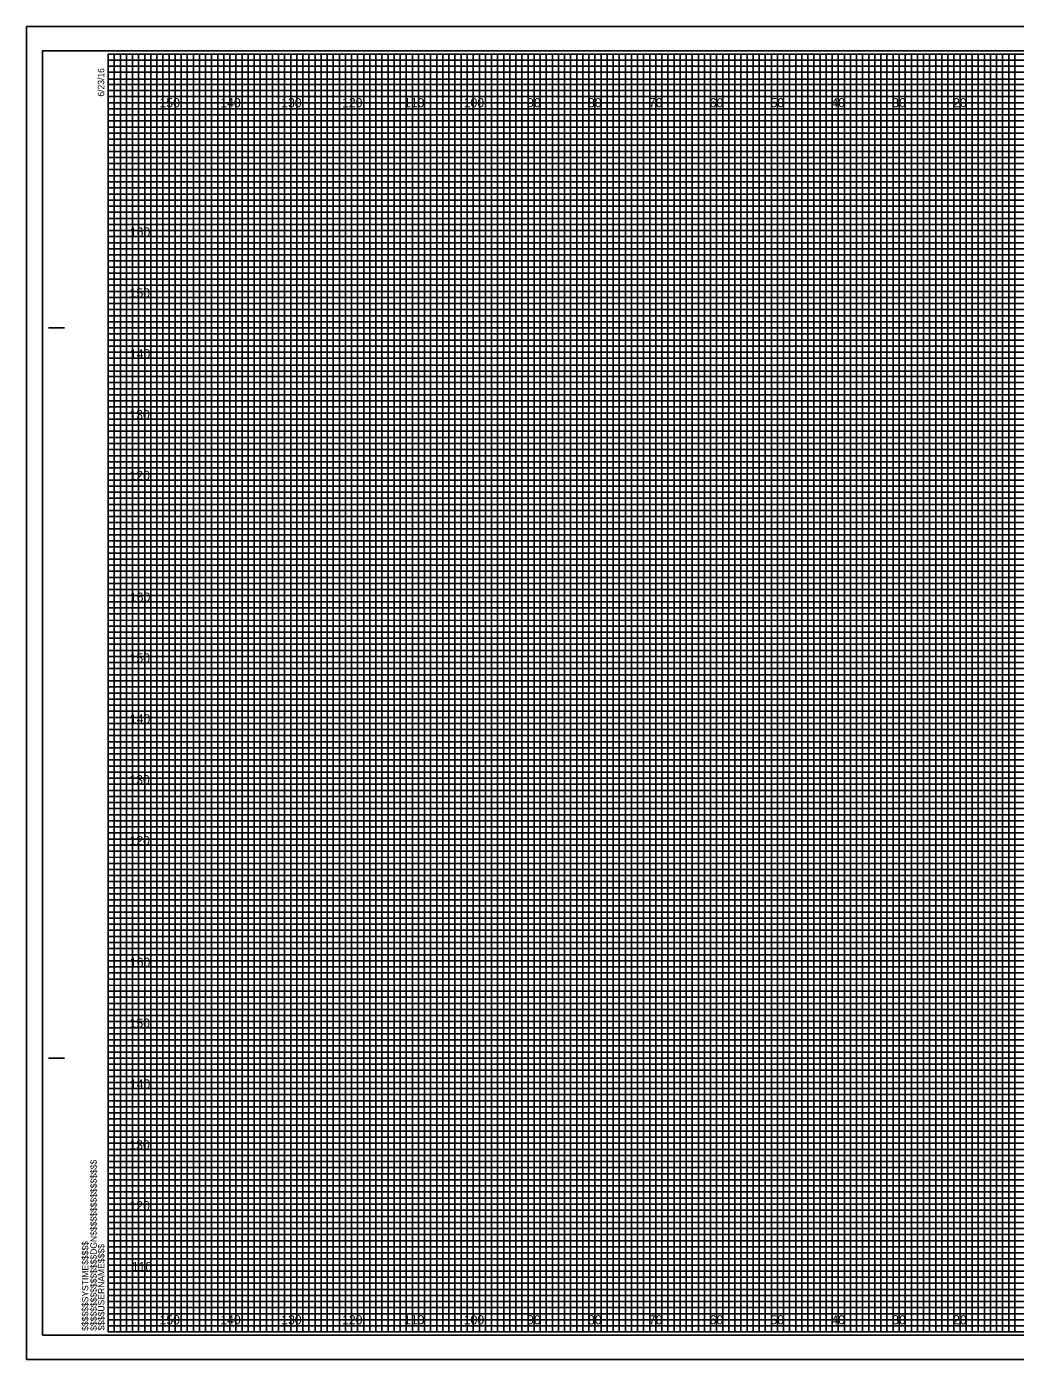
# Model space of a CAD drawing. Extents: x -13 to 323, y -5 to 1974.
# Drawn here: x -13.4 to 149.1, y 1095.5 to 1314.5 of the extents above; entities that cross this region are included whole.
import ezdxf

# ---------------------------------------------------------------- set-up
doc = ezdxf.new("R2010")
doc.units = 0
for name, color, linetype in [('Exist Cross Section Cell', 7, 'Continuous'), ('Exist XS Center Line Elevation Label', 7, 'Continuous'), ('Exist XS Ground Line', 7, 'Continuous'), ('Prop CMT Pvmt Course 1', 7, 'Continuous'), ('Prop CMT Pvmt Course 3', 7, 'Continuous'), ('Prop CMT Pvmt Surface', 7, 'Continuous'), ('Prop CMT Pvmt Surface Shoulder', 7, 'Continuous'), ('Prop CMT Shld Paved Course 1', 7, 'Continuous'), ('Prop CMT Shld Paved Course 2', 7, 'Continuous'), ('Prop CMT Shld Paved Course 3', 7, 'Continuous'), ('Prop CMT Subgrade Earthwork', 7, 'Continuous')]:
    doc.layers.add(name, color=color, linetype=linetype)

msp = doc.modelspace()

# ---------------------------------------------------------------- linework, layer by layer
at = {"layer": 'Exist XS Center Line Elevation Label'}
for points in [[(0, 1310), (5, 1310), (5, 1100), (15, 1100), (15, 1310), (25, 1310), (25, 1100), (35, 1100), (35, 1310), (45, 1310), (45, 1100), (55, 1100), (55, 1310), (65, 1310), (65, 1100), (75, 1100), (75, 1310), (85, 1310), (85, 1100), (95, 1100), (95, 1310), (105, 1310), (105, 1100), (115, 1100), (115, 1310), (125, 1310), (125, 1100), (135, 1100), (135, 1310), (145, 1310), (145, 1100), (155, 1100)], [(0, 1305), (275, 1305)], [(0, 1285), (320, 1285), (320, 1295), (0, 1295)], [(0, 1265), (320, 1265), (320, 1275), (0, 1275)], [(0, 1245), (320, 1245), (320, 1255), (0, 1255)], [(0, 1225), (320, 1225), (320, 1235), (0, 1235)], [(0, 1205), (320, 1205), (320, 1215), (0, 1215)], [(0, 1185), (320, 1185), (320, 1195), (0, 1195)], [(0, 1165), (320, 1165), (320, 1175), (0, 1175)], [(0, 1145), (320, 1145), (320, 1155), (0, 1155)], [(0, 1125), (320, 1125), (320, 1135), (0, 1135)], [(0, 1105), (320, 1105), (320, 1115), (0, 1115)]]:
    msp.add_lwpolyline(points, dxfattribs=at)
at = {"layer": 'Exist XS Ground Line'}
for p, q in [((10, 1310), (0, 1310)), ((10, 1100), (10, 1310)), ((30, 1310), (20, 1310)), ((20, 1310), (20, 1100)), ((30, 1100), (30, 1310)), ((50, 1310), (40, 1310)), ((40, 1310), (40, 1100)), ((50, 1100), (50, 1310)), ((70, 1310), (60, 1310)), ((60, 1310), (60, 1100)), ((70, 1100), (70, 1310)), ((90, 1310), (80, 1310)), ((80, 1310), (80, 1100)), ((90, 1100), (90, 1310)), ((110, 1310), (100, 1310)), ((100, 1310), (100, 1100)), ((110, 1100), (110, 1310)), ((130, 1310), (120, 1310)), ((120, 1310), (120, 1100)), ((130, 1100), (130, 1310)), ((150, 1310), (140, 1310)), ((140, 1310), (140, 1100)), ((20, 1100), (10, 1100)), ((40, 1100), (30, 1100)), ((60, 1100), (50, 1100)), ((80, 1100), (70, 1100)), ((100, 1100), (90, 1100)), ((120, 1100), (110, 1100)), ((140, 1100), (130, 1100))]:
    msp.add_line(p, q, dxfattribs=at)
for points in [[(0, 1300), (320, 1300), (320, 1290), (0, 1290)], [(0, 1280), (320, 1280), (320, 1270), (0, 1270)], [(0, 1260), (320, 1260), (320, 1250), (0, 1250)], [(0, 1240), (320, 1240), (320, 1230), (0, 1230)], [(0, 1220), (320, 1220), (320, 1210), (0, 1210)], [(0, 1200), (320, 1200), (320, 1190), (0, 1190)], [(0, 1180), (320, 1180), (320, 1170), (0, 1170)], [(0, 1160), (320, 1160), (320, 1150), (0, 1150)], [(0, 1140), (320, 1140), (320, 1130), (0, 1130)], [(0, 1120), (320, 1120), (320, 1110), (0, 1110)]]:
    msp.add_lwpolyline(points, dxfattribs=at)
at = {"layer": 'Prop CMT Pvmt Course 3'}
msp.add_lwpolyline([(-13.4, 1095.5), (323.3, 1095.5), (323.3, 1314.5), (-13.4, 1314.5)], close=True, dxfattribs=at)
at = {"layer": 'Prop CMT Pvmt Surface'}
for p, q in [((10, 1100), (10, 1310)), ((20, 1100), (20, 1310)), ((30, 1100), (30, 1310)), ((40, 1100), (40, 1310)), ((50, 1100), (50, 1310)), ((60, 1100), (60, 1310)), ((70, 1100), (70, 1310)), ((80, 1100), (80, 1310)), ((90, 1100), (90, 1310)), ((100, 1100), (100, 1310)), ((110, 1100), (110, 1310)), ((120, 1100), (120, 1310)), ((130, 1100), (130, 1310)), ((140, 1100), (140, 1310)), ((0, 1300), (320, 1300)), ((0, 1290), (320, 1290)), ((0, 1280), (320, 1280)), ((0, 1270), (320, 1270)), ((0, 1260), (320, 1260)), ((0, 1250), (320, 1250)), ((0, 1240), (320, 1240)), ((0, 1230), (320, 1230)), ((0, 1220), (320, 1220)), ((0, 1210), (320, 1210)), ((0, 1200), (320, 1200)), ((0, 1190), (320, 1190)), ((0, 1180), (320, 1180)), ((0, 1170), (320, 1170)), ((0, 1160), (320, 1160)), ((0, 1150), (320, 1150)), ((0, 1140), (320, 1140)), ((0, 1130), (320, 1130)), ((0, 1120), (320, 1120)), ((0, 1110), (320, 1110))]:
    msp.add_line(p, q, dxfattribs=at)
at = {"layer": 'Prop CMT Pvmt Surface Shoulder'}
for p, q in [((323.3, 1314.5), (-13.4, 1314.5)), ((-13.4, 1314.5), (-13.4, 1095.5)), ((-13.4, 1095.5), (323.3, 1095.5))]:
    msp.add_line(p, q, dxfattribs=at)
at = {"layer": 'Prop CMT Shld Paved Course 1'}
for p, q in [((0, 1309), (260, 1309)), ((260, 1307.98), (0, 1307.98)), ((0, 1307.98), (0, 1307)), ((0, 1307), (260, 1307)), ((260, 1305.89), (0, 1305.89)), ((0, 1305.89), (0, 1304)), ((0, 1304), (320, 1304))]:
    msp.add_line(p, q, dxfattribs=at)
for points in [[(0, 1303), (270, 1303), (320, 1303), (320, 1302), (0, 1302)], [(0, 1301), (320, 1301), (320, 1299), (0, 1299)], [(0, 1298), (320, 1298), (320, 1297), (0, 1296.98)], [(0, 1296), (320, 1296), (320, 1294), (0, 1294)], [(0, 1293), (320, 1293), (320, 1292), (0, 1292)], [(0, 1291), (320, 1291), (320, 1289), (0, 1289)], [(0, 1288), (320, 1288), (320, 1287), (0, 1287)], [(0, 1286), (320, 1286), (320, 1284), (0, 1284)], [(0, 1283), (320, 1283), (320, 1282), (0, 1282)], [(0, 1281), (320, 1281), (320, 1279), (0, 1279)], [(0, 1278), (320, 1278), (320, 1277), (0, 1277)], [(0, 1276), (320, 1276), (320, 1273.95), (320, 1273), (320, 1272), (0, 1272)], [(0, 1274), (320, 1274), (320, 1273), (0, 1273)], [(0, 1271), (320, 1271), (320, 1269), (0, 1269.03)], [(0, 1269.03), (320, 1269), (320, 1268), (0, 1268)], [(0, 1267), (320, 1267), (320, 1266), (0, 1266)], [(0, 1264), (320, 1264), (320, 1263), (0, 1263)], [(0, 1262), (320, 1262), (320, 1261), (0, 1261)], [(-0.07, 1258.89), (320, 1258.89), (320, 1257.88), (-0.07, 1257.88)], [(0, 1257), (320, 1257), (320, 1256), (0, 1256)], [(0, 1254), (320, 1254), (320, 1253), (0, 1253)], [(0, 1252), (320, 1252), (320, 1251), (0, 1251)], [(0, 1249), (320, 1249), (320, 1248), (0, 1248)], [(0, 1247), (320, 1247), (320, 1246), (0, 1246)], [(0, 1244), (320, 1244), (320, 1243), (0, 1243)], [(0, 1242), (320, 1242), (320, 1241), (0, 1241)], [(0, 1239), (320, 1239), (319.99, 1237.98), (0, 1238)], [(0, 1237), (320, 1237), (320, 1236), (0, 1236)], [(0, 1234), (320, 1234), (320, 1233), (0, 1233)], [(0, 1232), (320, 1232), (320, 1231), (0, 1231)], [(0, 1229), (320, 1229), (320, 1228), (0, 1228)], [(0, 1227), (320, 1227), (320, 1226), (0, 1226)], [(0, 1224), (320, 1224), (320, 1223), (0, 1223)], [(0, 1222), (320, 1222), (320, 1221), (0, 1221)], [(0, 1219), (320, 1219), (320, 1218), (0, 1218)], [(0, 1216.99), (320.07, 1216.91), (320, 1216), (0, 1216)], [(0, 1214), (320, 1214), (320, 1213), (0, 1213)], [(0, 1212), (320, 1212), (320, 1211), (0, 1211)], [(0, 1209), (320, 1209), (320, 1208), (0, 1208)], [(0, 1207), (320, 1207), (320, 1206), (0, 1206)], [(0, 1204), (320, 1204), (320, 1203), (0, 1203)], [(0, 1202), (320, 1202), (320, 1201), (0, 1201)], [(0, 1199), (320, 1199), (320, 1198), (0, 1198)], [(0, 1197), (320, 1197), (320, 1196), (0, 1196)], [(0, 1194), (320, 1194), (320, 1193), (0, 1193)], [(0, 1192), (320, 1192), (320, 1191), (0, 1191)], [(0, 1189), (320, 1189), (320, 1188), (0, 1188)], [(0, 1187), (320, 1187), (320, 1186), (0, 1186)], [(0, 1184), (320, 1184), (320, 1183), (0, 1183)], [(0, 1182), (320, 1182), (320, 1181), (0, 1181)], [(0, 1179), (320, 1179), (319.99, 1177.98), (0, 1178)], [(0, 1177), (320, 1177), (320, 1176), (0, 1176)], [(0, 1174), (320, 1174), (320, 1173), (0, 1173)], [(0, 1172), (320, 1172), (320, 1171), (0, 1171)], [(0, 1169), (320, 1169), (320, 1168), (0, 1168)], [(0, 1167), (320, 1167), (320, 1166), (0, 1166)], [(0, 1164), (320, 1164), (320, 1163), (0, 1163)], [(0, 1162), (320, 1162), (320, 1161), (0, 1161)], [(0, 1159), (320, 1159), (320, 1158), (0, 1158)], [(0, 1156.99), (320.07, 1156.91), (320, 1156), (0, 1156)], [(0, 1154), (320, 1154), (320, 1153), (0, 1153)], [(0, 1152), (320, 1152), (320, 1151), (0, 1151)], [(0, 1149), (320, 1149), (320, 1148), (0, 1148)], [(0, 1147), (320, 1147), (320, 1146), (0, 1146)], [(0, 1144), (320, 1144), (320, 1143), (0, 1143)], [(0, 1142), (320, 1142), (320, 1141), (0, 1141)], [(0, 1139), (320, 1139), (320, 1138), (0, 1138)], [(0, 1137), (320, 1137), (320, 1136), (0, 1136)], [(0, 1134), (320, 1134), (320, 1133), (0, 1133)], [(0, 1132), (320, 1132), (320, 1131), (0, 1131)], [(0, 1129), (320, 1129), (320, 1128), (0, 1128)], [(0, 1127), (320, 1127), (320, 1126), (0, 1126)], [(0, 1124), (320, 1124), (320, 1123), (0, 1123)], [(0, 1122), (320, 1122), (320, 1121), (0, 1121)], [(0, 1119), (320, 1119), (320, 1118), (0, 1118)], [(0, 1117), (320, 1117), (320, 1116), (0, 1116)], [(0, 1114), (320, 1114), (320, 1113), (0, 1113)], [(0, 1112), (320, 1112), (320, 1111), (0, 1111)], [(0, 1109), (320, 1109), (320, 1108), (0, 1108)], [(0, 1107), (320, 1107), (320, 1106), (0, 1106)], [(0, 1104), (320, 1104), (320, 1103), (0, 1103)], [(0, 1102), (320, 1102), (320, 1101), (0, 1101)]]:
    msp.add_lwpolyline(points, dxfattribs=at)
at = {"layer": 'Prop CMT Shld Paved Course 2'}
for p, q in [((-9.8, 1265), (-7.3, 1265)), ((-9.7, 1265), (-7.2, 1265)), ((-9.8, 1145), (-7.3, 1145)), ((-9.7, 1145), (-7.2, 1145)), ((0, 1100), (0, 1100)), ((0, 1100), (0, 1100)), ((0, 1100), (0, 1100)), ((0, 1100), (0, 1100)), ((0, 1100), (0, 1100)), ((0, 1100), (0, 1100)), ((0, 1100), (0, 1100))]:
    msp.add_line(p, q, dxfattribs=at)
msp.add_lwpolyline([(320, 1310), (0, 1310), (0, 1100), (320, 1100)], close=True, dxfattribs=at)
at = {"layer": 'Prop CMT Shld Paved Course 3'}
for points in [[(0, 1100), (1, 1100), (1, 1310), (2, 1310), (2, 1100)], [(2, 1100), (3, 1100), (3, 1310), (4, 1310), (4, 1100)], [(5, 1100), (6, 1100), (6, 1310), (7, 1310), (7, 1100)], [(7, 1100), (8, 1100), (8, 1310), (9, 1310), (9, 1100)], [(10, 1100), (11, 1100), (11, 1310), (12, 1310), (12, 1100)], [(12, 1100), (13, 1100), (13, 1310), (14, 1310), (14, 1100)], [(15, 1100), (16, 1100), (16, 1310), (17, 1310), (17, 1100)], [(17, 1100), (18, 1100), (18, 1310), (19, 1310), (19, 1100)], [(20, 1100), (21, 1100), (21, 1310), (22, 1310), (22, 1100)], [(22, 1100), (23, 1100), (23, 1310), (24, 1310), (24, 1100)], [(25, 1100), (26, 1100), (26, 1310), (27, 1310), (27, 1100)], [(27, 1100), (28, 1100), (28, 1310), (29, 1310), (29, 1100)], [(30, 1100), (31, 1100), (31, 1310), (32, 1310), (32, 1100)], [(32, 1100), (33, 1100), (33, 1310), (34, 1310), (34, 1100)], [(35, 1100), (36, 1100), (36, 1310), (37, 1310), (37, 1100)], [(37, 1100), (38, 1100), (38, 1310), (39, 1310), (39, 1100)], [(40, 1100), (41, 1100), (41, 1310), (42, 1310), (42, 1100)], [(42, 1100), (43, 1100), (43, 1310), (44, 1310), (44, 1100)], [(45, 1100), (46, 1100), (46, 1310), (47, 1310), (47, 1100)], [(47, 1100), (48, 1100), (48, 1310), (49, 1310), (49, 1100)], [(50, 1100), (51, 1100), (51, 1310), (52, 1310), (52, 1100)], [(52, 1100), (53, 1100), (53, 1310), (54, 1310), (54, 1100)], [(55, 1100), (56, 1100), (56, 1310), (57, 1310), (57, 1100)], [(57, 1100), (58, 1100), (58, 1310), (59, 1310), (59, 1100)], [(60, 1100), (61, 1100), (61, 1310), (62, 1310), (62, 1100)], [(62, 1100), (63, 1100), (63, 1310), (64, 1310), (64, 1100)], [(65, 1100), (66, 1100), (66, 1310), (67, 1310), (67, 1100)], [(67, 1100), (68, 1100), (68, 1310), (69, 1310), (69, 1100)], [(70, 1100), (71, 1100), (71, 1310), (72, 1310), (72, 1100)], [(72, 1100), (73, 1100), (73, 1310), (74, 1310), (74, 1100)], [(75, 1100), (76, 1100), (76, 1310), (77, 1310), (77, 1100)], [(77, 1100), (78, 1100), (78, 1310), (79, 1310), (79, 1100)], [(80, 1100), (81, 1100), (81, 1310), (82, 1310), (82, 1100)], [(82, 1100), (83, 1100), (83, 1310), (84, 1310), (84, 1100)], [(85, 1100), (86, 1100), (86, 1310), (87, 1310), (87, 1100)], [(87, 1100), (88, 1100), (88, 1310), (89, 1310), (89, 1100)], [(90, 1100), (91, 1100), (91, 1310), (92, 1310), (92, 1100)], [(92, 1100), (93, 1100), (93, 1310), (94, 1310), (94, 1100)], [(95, 1100), (96, 1100), (96, 1310), (97, 1310), (97, 1100)], [(97, 1100), (98, 1100), (98, 1310), (99, 1310), (99, 1100)], [(100, 1100), (101, 1100), (101, 1310), (102, 1310), (102, 1100)], [(102, 1100), (103, 1100), (103, 1310), (104, 1310), (104, 1100)], [(105, 1100), (106, 1100), (106, 1310), (107, 1310), (107, 1100)], [(107, 1100), (108, 1100), (108, 1310), (109, 1310), (109, 1100)], [(110, 1100), (111, 1100), (111, 1310), (112, 1310), (112, 1100)], [(112, 1100), (113, 1100), (113, 1310), (114, 1310), (114, 1100)], [(115, 1100), (116, 1100), (116, 1310), (117, 1310), (117, 1100)], [(117, 1100), (118, 1100), (118, 1310), (119, 1310), (119, 1100)], [(120, 1100), (121, 1100), (121, 1310), (122, 1310), (122, 1100)], [(122, 1100), (123, 1100), (123, 1310), (124, 1310), (124, 1100)], [(125, 1100), (126, 1100), (126, 1310), (127, 1310), (127, 1100)], [(127, 1100), (128, 1100), (128, 1310), (129, 1310), (129, 1100)], [(130, 1100), (131, 1100), (131, 1310), (132, 1310), (132, 1100)], [(132, 1100), (133, 1100), (133, 1310), (134, 1310), (134, 1100)], [(135, 1100), (136, 1100), (136, 1310), (137, 1310), (137, 1100)], [(137, 1100), (138, 1100), (138, 1310), (139, 1310), (139, 1100)], [(140, 1100), (141, 1100), (141, 1310), (142, 1310), (142, 1100)], [(142, 1100), (143, 1100), (143, 1310), (144, 1310), (144, 1100)], [(145, 1100), (146, 1100), (146, 1310), (147, 1310), (147, 1100)], [(147, 1100), (148, 1100), (148, 1310), (149, 1310), (149, 1100)]]:
    msp.add_lwpolyline(points, dxfattribs=at)
at = {"layer": 'Prop CMT Subgrade Earthwork'}
msp.add_lwpolyline([(-10.8, 1099.5), (322.4, 1099.5), (322.4, 1310.5), (-10.8, 1310.5)], close=True, dxfattribs=at)

# ---------------------------------------------------------------- texts
at = {"layer": 'Exist Cross Section Cell'}
for s, p in [('150', (8.44, 1301.25)), ('140', (18.44, 1301.25)), ('130', (28.44, 1301.25)), ('120', (38.44, 1301.25)), ('110', (48.62, 1301.25)), ('100', (58.44, 1301.25)), ('90', (68.86, 1301.25)), ('80', (78.86, 1301.25)), ('70', (88.86, 1301.25)), ('60', (98.86, 1301.25)), ('50', (108.86, 1301.25)), ('40', (118.86, 1301.25)), ('30', (128.86, 1301.25)), ('20', (138.86, 1301.25)), ('150', (8.44, 1101.25)), ('140', (18.44, 1101.25)), ('130', (28.44, 1101.25)), ('120', (38.44, 1101.25)), ('110', (48.62, 1101.25)), ('100', (58.44, 1101.25)), ('90', (68.86, 1101.25)), ('80', (78.86, 1101.25)), ('70', (88.86, 1101.25)), ('60', (98.86, 1101.25)), ('50', (108.86, 1101.25)), ('40', (118.86, 1101.25)), ('30', (128.86, 1101.25)), ('20', (138.86, 1101.25))]:
    msp.add_text(s, height=1.5, dxfattribs=at).set_placement(p)
at = {"layer": 'Prop CMT Pvmt Course 1'}
for s, p in [('160', (3.57, 1280)), ('150', (3.52, 1270)), ('140', (3.57, 1260)), ('130', (3.49, 1250)), ('120', (3.5, 1240)), ('160', (3.57, 1220)), ('150', (3.52, 1210)), ('140', (3.57, 1200)), ('130', (3.49, 1190)), ('120', (3.5, 1180)), ('160', (3.57, 1160)), ('150', (3.52, 1150)), ('140', (3.57, 1140)), ('130', (3.49, 1130)), ('120', (3.5, 1120)), ('110', (3.88, 1110))]:
    msp.add_text(s, height=1.5, dxfattribs=at).set_placement(p)
at = {"layer": 'Prop CMT Shld Paved Course 2'}
for s, p in [('6/23/16', (-0.65, 1303)), ('$$$$$$$$$$$$$$$$DGN$$$$$$$$$$$$$$$$', (-1.88, 1100.18)), ('$$$$$$SYSTIME$$$$$', (-3.26, 1100.18)), ('$$$$USERNAME$$$$', (-0.62, 1100.23))]:
    msp.add_text(s, height=1.05, rotation=90, dxfattribs=at).set_placement(p)

doc.saveas('drawing.dxf')
